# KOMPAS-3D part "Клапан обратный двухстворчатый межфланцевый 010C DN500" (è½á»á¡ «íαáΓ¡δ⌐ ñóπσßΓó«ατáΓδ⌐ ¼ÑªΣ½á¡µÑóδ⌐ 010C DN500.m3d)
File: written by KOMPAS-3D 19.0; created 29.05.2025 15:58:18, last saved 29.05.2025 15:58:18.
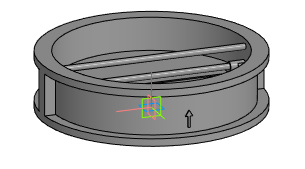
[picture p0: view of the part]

Document properties: Полное имя файла: E:\Dendor Работа Сачек\3D для проекитирвщиков\5.2 Тип 010C, 010C.Y Клапан обратный двухстворчатый межфланцевый\stp_Клапан обратный двухстворчатый межфланцевый 010C\Клапан обратный двухстворчатый межфланцевый 010C DN500.m3d

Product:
- Part/product: Клапан обратный двухстворчатый межфланцевый 010C DN500

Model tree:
1. Операция без истории:1  (labels: Клапан обратный двухстворчатый межфланцевый 010C DN500)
